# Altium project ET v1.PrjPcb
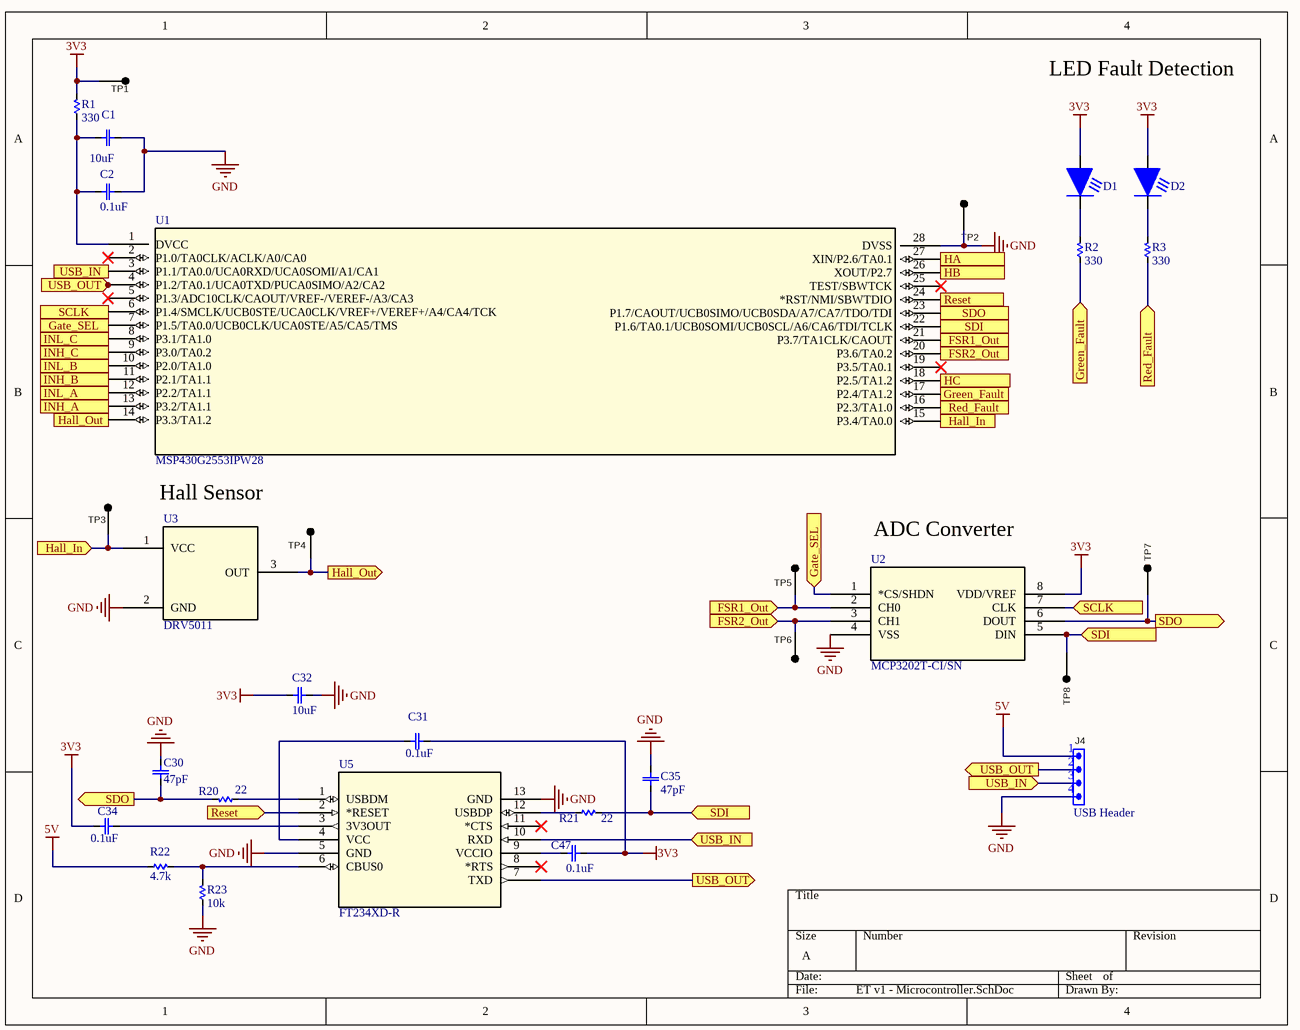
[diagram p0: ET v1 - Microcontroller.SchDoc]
2 sheets, 137 parts. Net scope: flat (ports and power ports of the same name join across sheets).
Board file: ET v1.PcbDoc
Sheets:
  ET v1 - Microcontroller.SchDoc
  ET v1 - GateDriver.SchDoc

## Sheet ET v1 - Microcontroller.SchDoc
size A

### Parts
C1  10uF  [1206]
C2  0.1uF  [1206]
C30  47pF  [0805_HV]
C31  0.1uF  [0805_HV]
C32  10uF  [1206]
C34  0.1uF  [0805_HV]
C35  47pF  [0805_HV]
C47  0.1uF  [0805_HV]
D1  LED  [LED_TH]  (value not drawn)
D2  LED  [LED_TH]  (value not drawn)
J4  USB Header  [USB Header]
R1  330  [0805_HV]
R2  330  [0805_HV]
R3  330  [0805_HV]
R20  22  [0805_HV]
R21  22  [0805_HV]
R22  4.7k  [1206]
R23  10k  [1206]
TP1  Test Point 1  [TP200_SMD]  (value not drawn)  (no BOM)
TP2  Test Point 1  [TP200_SMD]  (value not drawn)  (no BOM)
TP3  Test Point 1  [TP200_SMD]  (value not drawn)  (no BOM)
TP4  Test Point 1  [TP200_SMD]  (value not drawn)  (no BOM)
TP5  Test Point 1  [TP200_SMD]  (value not drawn)  (no BOM)
TP6  Test Point 1  [TP200_SMD]  (value not drawn)  (no BOM)
TP7  Test Point 1  [TP200_SMD]  (value not drawn)  (no BOM)
TP8  Test Point 1  [TP200_SMD]  (value not drawn)  (no BOM)
U1  MSP430G2553IPW28  [MSP430G2353IPW28]
U2  MCP3202T-CI/SN  [MCP3202T-CI/SN]
U3  DRV5011  [Hall_sensor]
U5  FT234XD-R  [FT234XD-R]

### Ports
FSR1_Out (in), FSR1_Out (out), FSR2_Out (in), FSR2_Out (out), Gate_SEL (in), Gate_SEL (out), Green_Fault (in), Green_Fault (out), HA (in), Hall_In (in), Hall_In (out), Hall_Out (in), Hall_Out (out), HB (in), HC (in), INH_A (out), INH_B (out), INH_C (out), INL_A (out), INL_B (out), INL_C (out), Red_Fault (in), Red_Fault (out), Reset (in), Reset (out), SCLK (in), SCLK (out), SDI (in), SDI (out), SDO (in), SDO (out), USB_IN (in), USB_IN (out), USB_OUT (in), USB_OUT (out)

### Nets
3V3: C31.1 C32.2 C34.1 C47.2 D1.1 D2.1 R1.2 TP1.1 U2.8(VDD/VREF)
5V: J4.1 R22.1
GND: C1.2 C2.2 C30.1 C32.1 C35.1 J4.4 R23.1 TP2.1 U1.28(DVSS) U2.4(VSS) U3.2(GND) U5.5(GND) U5.13(GND)
NetC1_1: C1.1 C2.1 R1.1 U1.1(DVCC)
NetC30_2: C30.2 R20.2 TP7.1 U1.23(P1.7/CAOUT/UCB0SIMO/UCB0SDA/A7/CA7/TDO/TDI) U2.6(DOUT) ; port SDO
NetC31_2: C31.2 U5.4(VCC)
NetC33_1: U1.18(P2.5/TA1.2) ; port HC
NetC34_2: C34.2 U5.3(3V3OUT)
NetC35_2: C35.2 R21.2 TP8.1 U1.22(P1.6/TA0.1/UCB0SOMI/UCB0SCL/A6/CA6/TDI/TCLK) U2.5(DIN) ; port SDI
NetC37_1: U1.26(XOUT/P2.7) ; port HB
NetC38_1: U1.27(XIN/P2.6/TA0.1) ; port HA
NetC47_1: C47.1 U5.9(VCCIO)
NetD1_2: D1.2 R2.2
NetD2_2: D2.2 R3.2
NetJ4_2: J4.2 U1.4(P1.2/TA0.1/UCA0TXD/PUCA0SIMO/A2/CA2) U5.7(TXD) ; port USB_OUT
NetJ4_3: J4.3 U1.3(P1.1/TA0.0/UCA0RXD/UCA0SOMI/A1/CA1) U5.10(RXD) ; port USB_IN
NetR2_1: R2.1 U1.17(P2.4/TA1.2) ; port Green_Fault
NetR3_1: R3.1 U1.16(P2.3/TA1.0) ; port Red_Fault
NetR20_1: R20.1 U5.1(USBDM)
NetR21_1: R21.1 U5.12(USBDP)
NetR22_2: R22.2 R23.2 U5.6(CBUS0)
NetTP3_1: TP3.1 U1.15(P3.4/TA0.0) U3.1(VCC) ; port Hall_In
NetTP4_1: TP4.1 U1.14(P3.3/TA1.2) U3.3(OUT) ; port Hall_Out
NetTP5_1: TP5.1 U1.21(P3.7/TA1CLK/CAOUT) U2.2(CH0) ; port FSR1_Out
NetTP6_1: TP6.1 U1.20(P3.6/TA0.2) U2.3(CH1) ; port FSR2_Out
NetTP16_1: U1.7(P1.5/TA0.0/UCB0CLK/UCA0STE/A5/CA5/TMS) U2.1(*CS/SHDN) ; port Gate_SEL
NetTP20_1: U1.13(P3.2/TA1.1) ; port INH_A
NetTP24_1: U1.11(P2.1/TA1.1) ; port INH_B
NetTP25_1: U1.9(P3.0/TA0.2) ; port INH_C
NetU1_6: U1.6(P1.4/SMCLK/UCB0STE/UCA0CLK/VREF+/VEREF+/A4/CA4/TCK) U2.7(CLK) ; port SCLK
NetU1_8: U1.8(P3.1/TA1.0) ; port INL_C
NetU1_10: U1.10(P2.0/TA1.0) ; port INL_B
NetU1_12: U1.12(P2.2/TA1.1) ; port INL_A
NetU1_24: U1.24(*RST/NMI/SBWTDIO) U5.2(*RESET) ; port Reset

Not connected (* = marked no-connect by the designer): U1 2(P1.0/TA0CLK/ACLK/A0/CA0)* 5(P1.3/ADC10CLK/CAOUT/VREF-/VEREF-/A3/CA3)* 19(P3.5/TA0.1)* 25(TEST/SBWTCK)*; U5 8(*RTS)* 11(*CTS)*

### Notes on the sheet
- LED Fault Detection
- Hall Sensor
- (near U2) ADC Converter

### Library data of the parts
C1 = C_10uF_CL31B106KOHVPJE: MLCC10UF16V 10 X7R1206; Manufacturer: TDK; Manufacturer Part Number: C3216X7R1V106M160AC; Voltage Rating: 35V; Tolerance: 20%; Dielectric: X7R; Dielectric Material: Ceramic
C2 = C_0.1uF 885012206020 CAP CER 0.1UF 10V X7R 0603: CAP CER 0.1UF 10V X7R 0603; Manufacturer: TDK; Manufacturer Part Number: C3216X7R2A104K160AA; Capacitance: 100nF; Tolerance: 10%; Voltage Rating: 100V
C30 C35 = C_47pF_C0805C470K5RAC7800: CAP CER 47PF 50V X7R 0805; Manufacturer: Samsung; Manufacturer Part Number: CL05A105MO5NNNC; Capacitance: 1uF; Tolerance: 20%; Voltage Rating: 16V
C31 C34 = C_0.1uF_C0805C104K6RAC7800: CAP CER SMD 0805 .1UF 35V 10% X7; Manufacturer: Wurth Electronics; Manufacturer Part Number: 885012105013; Capacitance: 2.2uF; Voltage Rating: 10V; Tolerance: 20%
C32 = C_10uF_CL31B106KOHVPJE: MLCC10UF16V 10 X7R1206; Manufacturer: TDK; Manufacturer Part Number: C3216X7R1V106M160AC; Dielectric Material: Ceramic; Voltage Rating: 35V; Tolerance: 20%; Dielectric: X7R
C47 = C_0.1uF_C0805C104K6RAC7800: CAP CER SMD 0805 .1UF 35V 10% X7
J4 = USB Header: 2.54mm pitch, 1mm hole; Manufacturer: Phoenix Contact; Manufacturer Part Number: 1904150; Number of Positions: 3; Gender: Male; Max Current Rating: 32A; Voltage Rating: 1kV; Number of Levels: 1; Current: 30A; Voltage: 600V; Max Supply Voltage: 800V; Pitch: 9.52mm; Wire Gauge (Max): 30AWG; Wire Gauge (Min): 10AWG; Wire/Cable Gauge: 24AWG; Approvals: CB
R1-R3 = R_ 330_ERJ-P6WJ331V: 330 Ohms ±1% 0.5W, 1/2W Chip Resistor 0805 (2012 Metric) Automotive AEC-Q200, Pulse Withstanding Thick Film
R20 R21 = R_22_ERJ-P06F22R0V: RES SMD 22 OHM 1% 1/2W 0805; Manufacturer: Vishay; Manufacturer Part Number: CRCW060347K0JNEA; Resistance: 47kR; Tolerance: 5%; Temperature Coefficient: 200ppm/°C; Max Power Dissipation: 100mW; Voltage Rating: 75V
R22 = R_4.7k CRGP1206F4K7: RES 4.7K OHM 1% 1/2W 1206; Manufacturer: Panasonic; Manufacturer Part Number: ERJ-2RKF1002X; Resistance: 10kR; Temperature Coefficient: 100ppm/°C; Power Rating: 100mW; Voltage Rating: 50V
R23 = R_10k_RE1206FRE0710KL: RES SMD 10K OHM 1% 1/4W 1206; Manufacturer: Vishay; Manufacturer Part Number: CRCW060347K0JNEA; Resistance: 47kR; Tolerance: 5%; Temperature Coefficient: 200ppm/°C; Max Power Dissipation: 100mW; Voltage Rating: 75V
TP1-TP8 = Test Point 1: Test Point, Round, Surface Pad
U1 = MSP430G2553IPW28: No Description Available; Mfr_Name: Texas Instruments
U2 = MCP3202T-CI/SN: IC ADC 12BIT SAR 8SOIC; Mfr_Name: Microchip
U3 = Hall_Sensor_DRV5011: MAGNETIC SWITCH LATCH TO92-3
U5 = FT234XD-R: IC USB SERIAL BASIC UART 12DFN; Mfr_Name: FTDI, Future Technology Devices International Ltd

## Sheet ET v1 - GateDriver.SchDoc
size B
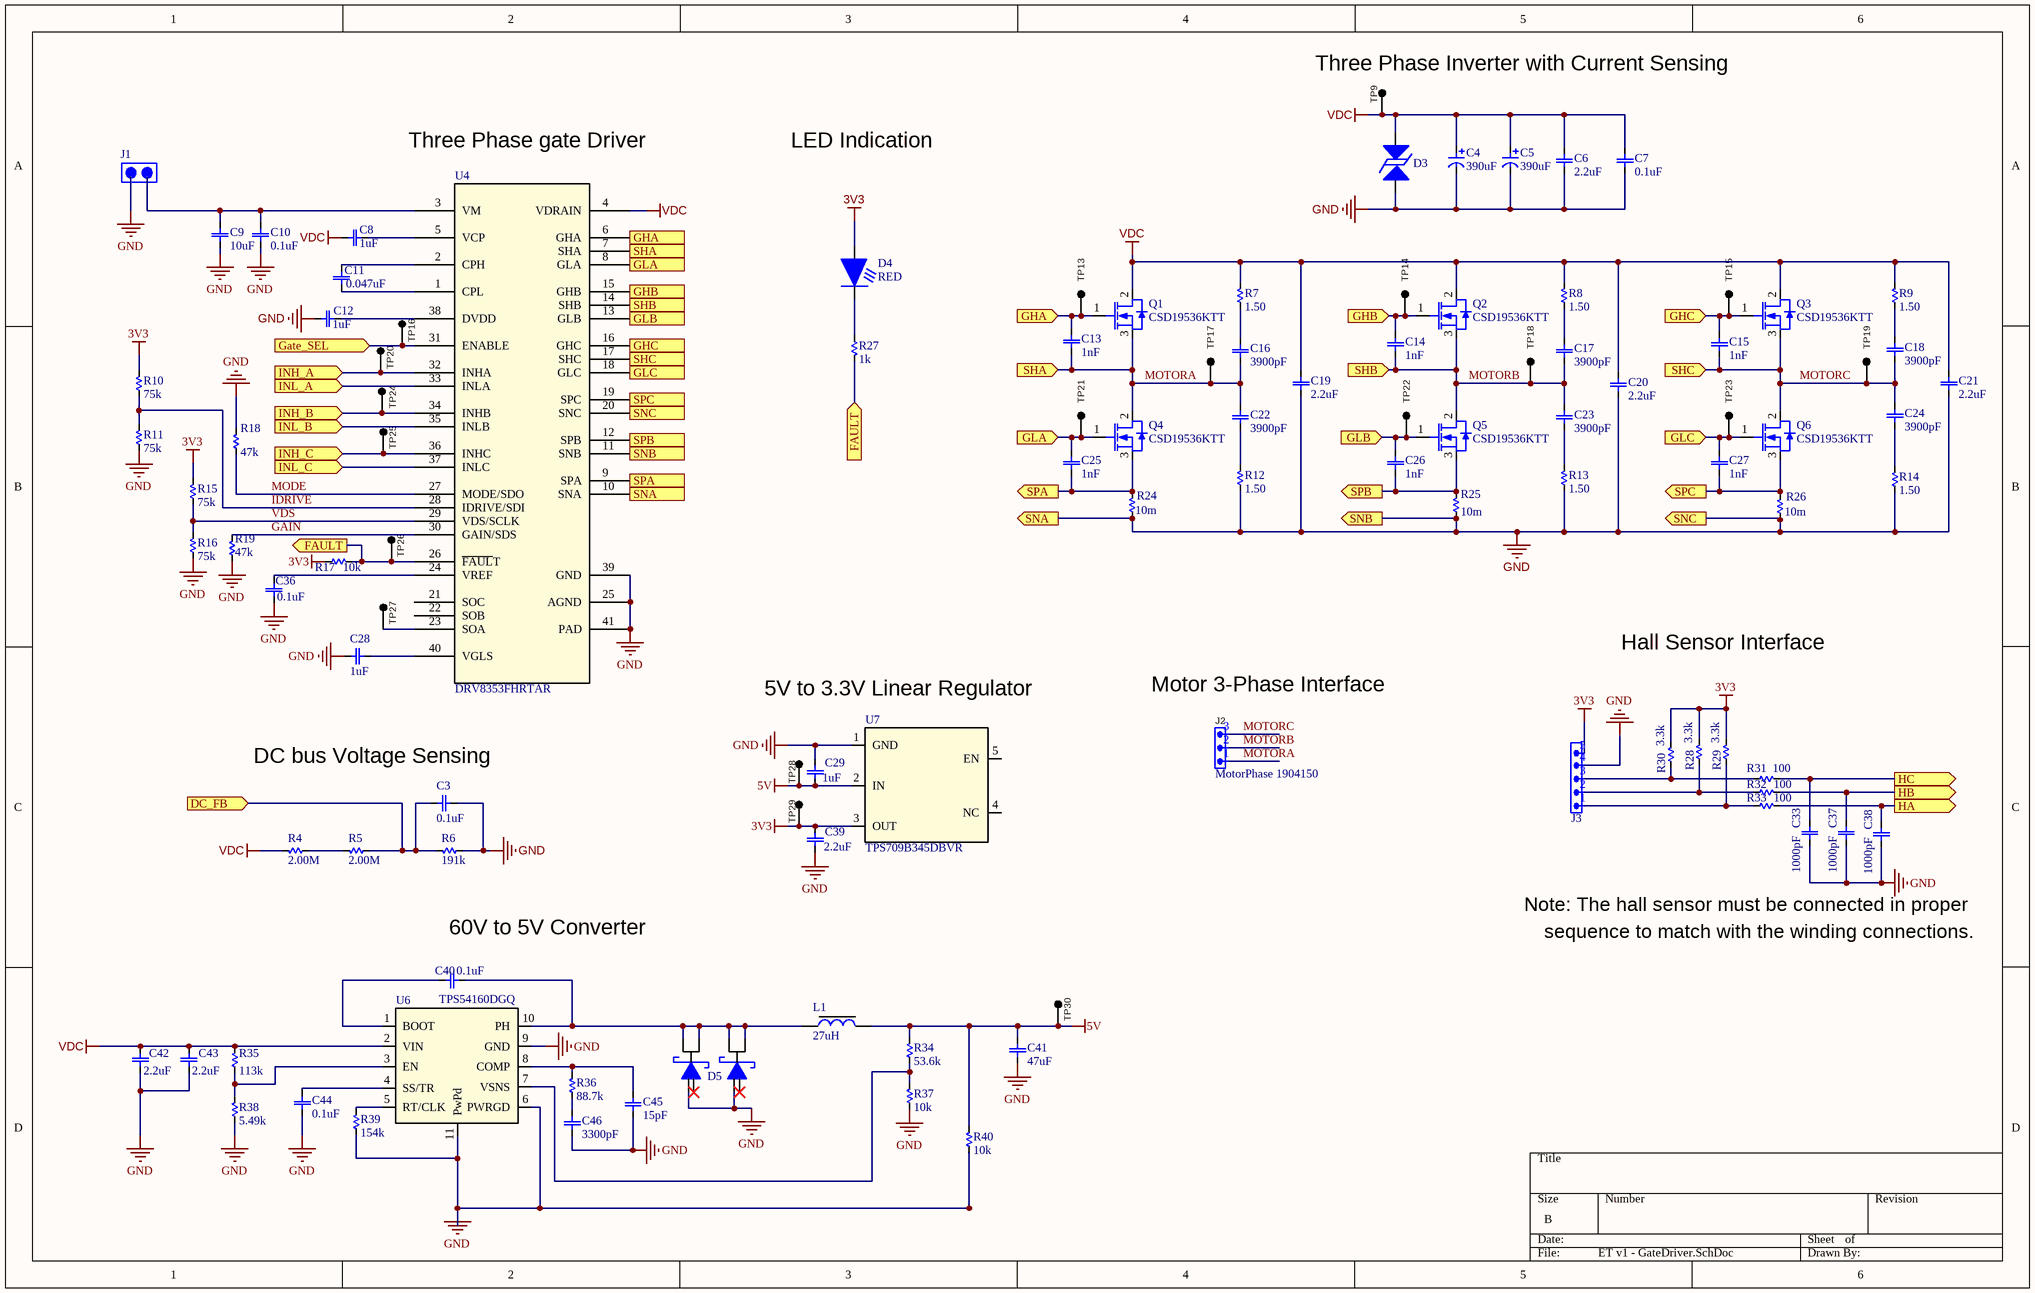
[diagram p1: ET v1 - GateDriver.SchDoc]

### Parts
C3  0.1uF  [1206]
C4  390uF  [YXJ_1600x2500]
C5  390uF  [YXJ_1600x2500]
C6  2.2uF  [1206]
C7  0.1uF  [1206]
C8  1uF  [0805_HV]
C9  10uF  [2220_280]
C10  0.1uF  [0603]
C11  0.047uF  [0805_HV]
C12  1uF  [0805_HV]
C13  1nF  [0603]
C14  1nF  [0603]
C15  1nF  [0603]
C16  3900pF  [1206]
C17  3900pF  [1206]
C18  3900pF  [1206]
C19  2.2uF  [1206]
C20  2.2uF  [1206]
C21  2.2uF  [1206]
C22  3900pF  [1206]
C23  3900pF  [1206]
C24  3900pF  [1206]
C25  1nF  [0603]
C26  1nF  [0603]
C27  1nF  [0603]
C28  1uF  [0805_HV]
C29  1uF  [0805_HV]
C33  1000pF  [0805_HV]
C36  0.1uF  [1206]
C37  1000pF  [0805_HV]
C38  1000pF  [0805_HV]
C39  2.2uF  [1206]
C40  0.1uF  [1206]
C41  47uF  [0805_HV]
C42  2.2uF  [0402]
C43  2.2uF  [0402]
C44  0.1uF  [1206]
C45  15pF  [0805_HV]
C46  3300pF  [0805_HV]
D3  SMBJ70CA-13-F  [SMB-Bi]  (value not drawn)
D4  RED  [WL-SMCW_GREEN]
D5  V8KM60DUHM3/H  [V8KM60DUHM3/H]  (value not drawn)
J1  XT60 PRT-10474  [XT60 PRT-10474]  (value not drawn)
J2  MotorPhase 1904150  [MotorPhase 1904150]
J3  MotorHall_1792892  [MotorHall_1792892]  (value not drawn)
L1  27uH  [MSS1038T-273MLC]
Q1  CSD19536KTT  [KTT0002A]
Q2  CSD19536KTT  [KTT0002A]
Q3  CSD19536KTT  [KTT0002A]
Q4  CSD19536KTT  [KTT0002A]
Q5  CSD19536KTT  [KTT0002A]
Q6  CSD19536KTT  [KTT0002A]
R4  2.00M  [0402]
R5  2.00M  [0402]
R6  191k  [0603]
R7  1.50  [1206]
R8  1.50  [1206]
R9  1.50  [1206]
R10  75k  [0603]
R11  75k  [0603]
R12  1.50  [1206]
R13  1.50  [1206]
R14  1.50  [1206]
R15  75k  [0603]
R16  75k  [0603]
R17  10k  [0603]
R18  47k  [0603]
R19  47k  [0603]
R24  10m  [2512]
R25  10m  [2512]
R26  10m  [2512]
R27  1k  [0805_HV]
R28  3.3k  [0805_HV]
R29  3.3k  [0805_HV]
R30  3.3k  [0805_HV]
R31  100  [0805_HV]
R32  100  [0805_HV]
R33  100  [0805_HV]
R34  53.6k  [0805_HV]
R35  113k  [0805_HV]
R36  88.7k  [0805_HV]
R37  10k  [1206]
R38  5.49k  [0805_HV]
R39  154k  [0805_HV]
R40  10k  [1206]
TP9  Test Point 1  [TP200_SMD]  (value not drawn)  (no BOM)
TP13  Test Point 1  [TP200_SMD]  (value not drawn)  (no BOM)
TP14  Test Point 1  [TP200_SMD]  (value not drawn)  (no BOM)
TP15  Test Point 1  [TP200_SMD]  (value not drawn)  (no BOM)
TP16  Test Point 1  [TP200_SMD]  (value not drawn)  (no BOM)
TP17  Test Point 1  [TP200_SMD]  (value not drawn)  (no BOM)
TP18  Test Point 1  [TP200_SMD]  (value not drawn)  (no BOM)
TP19  Test Point 1  [TP200_SMD]  (value not drawn)  (no BOM)
TP20  Test Point 1  [TP200_SMD]  (value not drawn)  (no BOM)
TP21  Test Point 1  [TP200_SMD]  (value not drawn)  (no BOM)
TP22  Test Point 1  [TP200_SMD]  (value not drawn)  (no BOM)
TP23  Test Point 1  [TP200_SMD]  (value not drawn)  (no BOM)
TP24  Test Point 1  [TP200_SMD]  (value not drawn)  (no BOM)
TP25  Test Point 1  [TP200_SMD]  (value not drawn)  (no BOM)
TP26  Test Point 1  [TP200_SMD]  (value not drawn)  (no BOM)
TP27  Test Point 1  [TP200_SMD]  (value not drawn)  (no BOM)
TP28  Test Point 1  [TP200_SMD]  (value not drawn)  (no BOM)
TP29  Test Point 1  [TP200_SMD]  (value not drawn)  (no BOM)
TP30  Test Point 1  [TP200_SMD]  (value not drawn)  (no BOM)
U4  DRV8353FHRTAR  [DRV8353FHRTAR]
U6  TPS54160DGQ  [TPS54160DGQ]
U7  TPS709B345DBVR  [TPS709B345DBVR]

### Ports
DC_FB (in), FAULT (in), FAULT (out), Gate_SEL (in), GHA (in), GHA (out), GHB (in), GHB (out), GHC (in), GHC (out), GLA (in), GLA (out), GLB (in), GLB (out), GLC (in), GLC (out), HA (out), HB (out), HC (out), INH_A (in), INH_B (in), INH_C (in), INL_A (in), INL_B (in), INL_C (in), SHA (in), SHB (in), SHC (in), SNA (in), SNA (out), SNB (in), SNB (out), SNC (in), SNC (out), SPA (in), SPA (out), SPB (in), SPB (out), SPC (in), SPC (out)

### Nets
3V3: C39.2 D4.1 J3.5 R10.2 R15.2 R17.1 R28.2 R29.2 R30.2 TP29.1 U7.3(OUT)
5V: C29.1 C41.2 L1.2 R34.2 R40.2 TP28.1 TP30.1 U7.2(IN)
GND: C3.1 C4.2 C5.2 C6.1 C7.1 C9.1 C10.1 C12.1 C19.1 C20.1 C21.1 C28.1 C29.2 C33.2 C36.1 C37.2 C38.2 C39.1 C41.1 C42.1 C43.1 C44.1 C45.1 C46.1 D3.1 D5.1 D5.3 J1.1 J3.4 R6.1 R11.1 R12.1 R13.1 R14.1 R16.1 R18.2 R19.1 R24.1 R25.1 R26.1 R37.1 R38.1 R39.1 R40.1 U4.10(SNA) U4.11(SNB) U4.20(SNC) U4.25(AGND) U4.39(GND) U4.41(PAD) U6.6(PWRGD) U6.9(GND) U6.11(PwPd) U7.1(GND) ; port SNC, port SNB, port SNA
VDC: C4.1 C5.1 C6.2 C7.2 C8.1 C19.2 C20.2 C21.2 C42.2 C43.2 D3.2 Q1.2 Q2.2 Q3.2 R4.2 R7.2 R8.2 R9.2 R35.2 TP9.1 U4.4(VDRAIN) U6.2(VIN)
GAIN: R19.2 U4.30(GAIN/SDS)
IDRIVE: R10.1 R11.2 U4.28(IDRIVE/SDI)
MODE: R18.1 U4.27(MODE/SDO)
MOTORA: C13.1 C16.1 C22.2 J2.1 Q1.3 Q4.2 TP17.1 U4.7(SHA) ; port SHA
MOTORB: C14.1 C17.1 C23.2 J2.2 Q2.3 Q5.2 TP18.1 U4.14(SHB) ; port SHB
MOTORC: C15.1 C18.1 C24.2 J2.3 Q3.3 Q6.2 TP19.1 U4.17(SHC) ; port SHC
VDS: R15.1 R16.2 U4.29(VDS/SCLK)
NetC3_2: C3.2 R5.1 R6.2 ; port DC_FB
NetC8_2: C8.2 U4.5(VCP)
NetC9_2: C9.2 C10.2 J1.2 U4.3(VM)
NetC11_1: C11.1 U4.1(CPL)
NetC11_2: C11.2 U4.2(CPH)
NetC12_2: C12.2 U4.38(DVDD)
NetC13_2: C13.2 Q1.1 TP13.1 U4.6(GHA) ; port GHA
NetC14_2: C14.2 Q2.1 TP14.1 U4.15(GHB) ; port GHB
NetC15_2: C15.2 Q3.1 TP15.1 U4.16(GHC) ; port GHC
NetC16_2: C16.2 R7.1
NetC17_2: C17.2 R8.1
NetC18_2: C18.2 R9.1
NetC22_1: C22.1 R12.2
NetC23_1: C23.1 R13.2
NetC24_1: C24.1 R14.2
NetC25_1: C25.1 Q4.3 R24.2 U4.9(SPA) ; port SPA
NetC25_2: C25.2 Q4.1 TP21.1 U4.8(GLA) ; port GLA
NetC26_1: C26.1 Q5.1 TP22.1 U4.13(GLB) ; port GLB
NetC26_2: C26.2 Q5.3 R25.2 U4.12(SPB) ; port SPB
NetC27_1: C27.1 Q6.3 R26.2 U4.19(SPC) ; port SPC
NetC27_2: C27.2 Q6.1 TP23.1 U4.18(GLC) ; port GLC
NetC28_2: C28.2 U4.40(VGLS)
NetC33_1: C33.1 R31.2 ; port HC
NetC36_2: C36.2 U4.24(VREF)
NetC37_1: C37.1 R32.2 ; port HB
NetC38_1: C38.1 R33.2 ; port HA
NetC40_1: C40.1 U6.1(BOOT)
NetC40_2: C40.2 D5.5 D5.6 D5.7 D5.8 L1.1 U6.10(PH)
NetC44_2: C44.2 U6.4(SS/TR)
NetC45_2: C45.2 R36.2 U6.8(COMP)
NetC46_2: C46.2 R36.1
NetD4_2: D4.2 R27.1
NetJ3_1: J3.1 R29.1 R33.1
NetJ3_2: J3.2 R28.1 R32.1
NetJ3_3: J3.3 R30.1 R31.1
NetR4_1: R4.1 R5.2
NetR17_2: R17.2 R27.2 TP26.1 U4.26(~{FAUL}T) ; port FAULT
NetR34_1: R34.1 R37.2 U6.7(VSNS)
NetR35_1: R35.1 R38.2 U6.3(EN)
NetR39_2: R39.2 U6.5(RT/CLK)
NetTP16_1: TP16.1 U4.31(ENABLE) ; port Gate_SEL
NetTP20_1: TP20.1 U4.32(INHA) ; port INH_A
NetTP24_1: TP24.1 U4.34(INHB) ; port INH_B
NetTP25_1: TP25.1 U4.36(INHC) ; port INH_C
NetTP27_1: TP27.1 U4.23(SOA)
NetU1_8: U4.37(INLC) ; port INL_C
NetU1_10: U4.35(INLB) ; port INL_B
NetU1_12: U4.33(INLA) ; port INL_A

Not connected (* = marked no-connect by the designer): D5 2* 4*; U4 21(SOC) 22(SOB); U7 4(NC) 5(EN)

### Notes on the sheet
- (near TP9) Three Phase Inverter with Current Sensing
- Three Phase gate Driver
- LED Indication
- Hall Sensor Interface
- 5V to 3.3V Linear Regulator
- (near J2) Motor 3-Phase Interface
- (near C3) DC bus Voltage Sensing
- Note: The hall sensor must be connected in proper
- 60V to 5V Converter
- sequence to match with the winding connections.

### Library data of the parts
C3 = C_0.1uF 885012208009: CAP CER 0.1UF 10V X7R 1206
C4 C5 = C_390uF EEU-FS2A391: CAP ALUM 390UF 20% 100V THRUHOLE; Manufacturer: Panasonic
C6 C19-C21 C39 = C_2.2uF CL31B225KCHSNNE: Cap Ceramic 2.2uF 100V X7R 10% Pad SMD 1206 Soft Termination 125C T/R; Manufacturer: Samsung
C7 = C_0.1uF C3216X7R2A104K160AA: CAP CER 0.1UF 100V X7R 1206; Manufacturer: TDK; Capacitance: 100nF; Tolerance: 10%
C8 C28 C29 = C_1uF CGA4J2X5R1C105M125AA: 1 µF ±20% 16V Ceramic Capacitor X5R 0805 (2012 Metric)
C9 = C_10uF 22201C106MAT2A: Cap Ceramic 10uF 100V X7R 20% SMD 2220 125°C Embossed T/R; Manufacturer: Kyocera AVX; Number of Outputs: 1; Output Voltage: 58V; Output Current: 1.5A; Switching Frequency: 581kHz; Max Input Voltage: 60V; Min Input Voltage: 3.5V; Synchronous Rectifier: No; Min Output Voltage: 800mV; Quiescent Current: 116uA; Output Type: Adjustable; Topology: Buck-Boost
C10 = C_0.1uF GRM188R72A104KA35D: 0603 0.1 uF 100 V ±10 % Tolerance X7R SMT Multilayer Ceramic Capacitor; Manufacturer: Murata; Capacitance: 100nF; Tolerance: 10%; Voltage Rating: 100V
C11 = C_0.047uF GRM21BR72A473KA01L: Cap Ceramic 0.047uF 100V X7R 10% SMD 0805 125C Embossed T/R; Manufacturer: Murata; Capacitance: 47nF
C12 = C_1uF LGC26D105MAT2S1: CAP CER 1UF 6.3V X5R 0805
C13-C15 C25-C27 = C_1nF 885012206083: CAP, CERM, 1000 pF, 50 V,+/- 10%, X7R, 0603
C16-C18 C22-C24 = C_3900pF 12061C392KAZ2A: CAP CER 3900PF 100V X7R 1206
C33 C37 C38 = C_1000pF CC0805JRNPO9BN102: Capacitor 1NF 50V 0805 SMD Npo (reel); Manufacturer: Yageo; Dielectric Material: Ceramic; Tolerance: 5%; Dielectric: C0G; Insulation Resistance: 10GR; Temperature Coefficient: 30ppm/°C; Dissipation Factor: 0.1%
C36 C40 C44 = C_0.1uF 885012206020 CAP CER 0.1UF 10V X7R 0603: as C2 on sheet ET v1 - Microcontroller
C41 = C_47uF C0805C476M9PACTU: Cap Ceramic 47uF 6.3V X5R 20% SMD 0805 Plastic T/R; Manufacturer: KEMET; Dissipation Factor: 5%
C42 C43 = C_2.2uF 885012105013: Cap, 2.2UF, 10V, 20%, X5R, 0402; Manufacturer: Wurth Electronics
C45 = C_15pF 08055A150GAT2A: Capacitor, ceramic, 15Pf, 50Vdc, 2-% Tol, 2+% Tol, c0G-Tc Code, -30, 30Ppm-Tc Rohs Compliant: Yes; Manufacturer: Kyocera AVX; Tolerance: 2%; Dielectric: C0G; Voltage Rating: 50V
C46 = C_3300pF 885012207119: Cap, 3300PF, 100V, 10%, X7R, 0805; Manufacturer: Wurth Electronics; Capacitance: 3.3nF
D3 = Diode SMBJ70CA-13-F: Diode TVS Single Bi-Dir 70V 600W 2-Pin SMB T/R; Manufacturer: Diodes; Manufacturer Part Number: SMBJ7.0CA-13-F; Number of Terminals/Pins: 2; Package Body Material: Plastic; Diode Element Material: SILICON; Min Breakdown Voltage: 77.8V; Clamping Voltage: 113V; Peak Pulse Current: 5.3A; Direction: Bidirectional; Max Reverse Leakage Current: 5uA; Test Current: 1mA; Max Breakdown Voltage: 89.5V; Reverse Breakdown Voltage: 7.78V; Number of Elements: 1; Power Line Protection: No; Leakage Current: 400uA; Voltage Rating (DC): 7V; Diode Type: ZENER; Time @ Peak Reflow Temperature-Max (s): 5s
D4 = LED_Red 150060RS75000: LED Low-Power Uni-Color Red 630nm 2V 2-Pin Chip 0603(1608Metric) T/R; Manufacturer: Wurth Electronics; Viewing Angle: 140°; Lens Style: Clear,Rectangular; Luminous Intensity: 250mcd; Forward Current: 30mA; Wavelength: 625nm; Test Current: 20mA
D5 = Diode V8KM60DUHM3/H: Diode Array 2 Independent Schottky 60 V 8A Surface Mount 8-PowerTDFN
J1 = XT60 PRT-10474: XT60 Connectors Male/female Pair; Manufacturer: SparkFun
J2 = MotorPhase 1904150: Conn PC Terminal Block 3 POS 9.52mm Solder ST Thru-Hole 32A; Manufacturer: Phoenix Contact; Number of Positions: 3; Gender: Male; Voltage Rating: 1kV; Number of Levels: 1; Current: 30A; Voltage: 600V; Max Supply Voltage: 800V; Wire Gauge (Max): 30AWG; Wire Gauge (Min): 10AWG; Wire/Cable Gauge: 24AWG; Approvals: CB
J3 = MotorHall_1792892: Wire-To-Board Terminal Block, 5, 400 V, 12 A, 26 Awg, 14 Awg, 2.5 Mm Rohs Compliant: Yes; Manufacturer: Phoenix Contact; Current Rating: 10A; Voltage Rating: 300V; Number of Contacts: 5; Number of Levels: 1; Wire Gauge (Max): 26AWG; Wire Gauge (Min): 14AWG; Pitch: 5mm; Stripping Length: 8mm; Approvals: VDE,cULus,CB,EAC
L1 = L_27uH MSS1038T-273MLC: Power inductor, shielded, 10/20/30% tol, SMT, RoHS; Manufacturer: Coilcraft; Core Material: Ferrite; Inductance Tolerance: 20%; Self Resonant Frequency: 15MHz; Max DC Current: 2.35A; DC Resistance (DCR): 89mR; Test Frequency: 100kHz; Saturation Current: 1.98A
Q1-Q6 = MOSFET CSD19536KTT: This 100 V, 2.0 m D2PAK (TO-263) NexFET power MOSFET is designed to minimize losses in power conversion applications.; Manufacturer: Texas Instruments; Drain to Source Voltage (Vdss): 100V; Continuous Drain Current (ID): 200A; Rds On Max: 2.4mR; Input Capacitance: 12nF; Max Power Dissipation: 375W; Fall Time: 6ns; Gate to Source Voltage (Vgs): 20V; Rise Time: 8ns; Turn-On Delay Time: 13ns; Turn-Off Delay Time: 32ns; Element Configuration: Single
R4 R5 = R_2M CRCW04022M00FKED: Res Thick Film 0402 2M Ohm 1% 1/16W ±100ppm/°C Molded SMD SMD Paper T/R; Manufacturer: Vishay; Resistance: 2MR; Power Rating: 63mW; Voltage Rating: 50V
R6 = R_191k RC0603FR-07191KL: RES 191K OHM 1% 1/10W 0603
R7-R9 R12-R14 = R_1.50 CRCW12061R50FKEA: Thick Film Resistors - SMD 1/4watt 1.5ohms 1%; Manufacturer: Vishay Dale; Resistance: 1.5R; Temperature Coefficient: 100ppm/°C; Power Rating: 250mW; Voltage Rating: 200V
R10 R11 R15 R16 = R_75k CRCW060375K0JNEA: Res Thick Film 0603 75K Ohm 5% 1/10W ±200ppm/°C Molded SMD SMD Paper T/R; Manufacturer: Vishay Dale; Resistance: 75kR; Max Power Dissipation: 100mW; Voltage Rating: 75V
R17 = R_10k RC0603FR-0710KL: RES 10K OHM 1% 1/10W 0603
R18 R19 = R_47k CRCW060347K0JNEA: Res Thick Film 0603 47K Ohm 5% 1/10W ±200ppm/°C Molded SMD SMD Paper T/R; Manufacturer: Vishay; Resistance: 47kR; Max Power Dissipation: 100mW; Voltage Rating: 75V
R24-R26 = R_10m CSR2512A0R01F: Res 2512 0.01 Ohm 1% 2W ±50/±75ppm/C Pad SMD T/R; Manufacturer: Riedon; Resistance: 10mR; Temperature Coefficient: 50ppm/°C
R27 = R_1k CR0805-FX-1001ELF: Res Thick Film 0805 1K Ohm 1% 1/8W ±100ppm/°C Molded SMD SMD Paper Tape on Plastic Reel; Manufacturer: Bourns; Resistance: 1kR; Power Rating: 125mW; Voltage Rating: 150V
R28-R30 = R_3.3k SR0805FR-473K3L: Res Thick Film 0805 3.3K Ohm 1% 0.5W(1/2W) ±100ppm/°C Pad SMD Automotive T/R; Manufacturer: Yageo
R31-R33 = R_100 SR0805JR-47100RL: Res Thick Film 0805 100 Ohm 5% 0.5W(1/2W) ±100ppm/C Pad SMD Automotive T/R; Manufacturer: Yageo
R34 = R_53.6k RT0805FRE0753K6L: High Precision-High Stability Chip Resistor Thin Film 0805 53.6kOhm 1% Paper T/R; Manufacturer: Yageo; Resistance: 53.6kR; Power Rating: 125mW; Voltage Rating: 150V; Temperature Coefficient: 50ppm/°C
R35 = R_113k CRCW0805113KFKEA: Res Thick Film 0805 113K Ohm 1% 1/8W ±100ppm/°C Molded SMD SMD Paper T/R; Manufacturer: Vishay; Resistance: 113kR; Max Power Dissipation: 125mW; Voltage Rating: 150V
R36 = R_88.7k RC0805FR-0788K7L: Res Thick Film 0805 88.7K Ohm 1% 0.125W(1/8W) ±100ppm/C Pad SMD T/R; Manufacturer: Yageo; Resistance: 88.7kR; Power Rating: 125mW; Voltage Rating: 150V; Temperature Coefficient: 100ppm/°C
R37 R40 = R_10k_RE1206FRE0710KL: as R23 on sheet ET v1 - Microcontroller
R38 = R_5.49k RC0805FR-075K49L: Res Thick Film 2.0 x 1.2 mm 5.49K Ohm 1% 0.125W(1/8W) 100ppm/ C Molded SMD Paper T/R; Manufacturer: Yageo; Power Rating: 125mW; Resistance: 5.49kR; Voltage Rating: 150V; Temperature Coefficient: 100ppm/°C
R39 = R_154k RC0805FR-07154KL: Res Thick Film 2.0 x 1.2 mm 154K Ohm 1% 0.125W(1/8W) 100ppm/ C Molded SMD Paper T/R; Manufacturer: Yageo; Resistance: 154kR; Temperature Coefficient: 100ppm/°C; Power Rating: 125mW; Voltage Rating: 150V
TP9 TP13-TP30 = Test Point 1: Test Point, Round, Surface Pad
U6 = TPS54160DGQ: 3.5V to 60V Input, 1.5A Step-Down Converter with Eco-Mode 10-HVSSOP -40 to 150; Manufacturer: Texas Instruments; Number of Outputs: 1; Output Voltage: 58V; Switching Frequency: 581kHz; Synchronous Rectifier: No; Min Output Voltage: 800mV; Quiescent Current: 116uA; Output Type: Adjustable; Topology: Buck-Boost
U7 = TPS709B345DBVR: Voltage Regulator with Enable 3.45V 150mA 1uA IQ 5-Pin SOT-23 T/R; Manufacturer: Texas Instruments

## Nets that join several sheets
3V3: ET v1 - Microcontroller (9 pins), ET v1 - GateDriver (11 pins)
5V: ET v1 - Microcontroller (J4.1 R22.1), ET v1 - GateDriver (8 pins)
GND: ET v1 - Microcontroller (13 pins), ET v1 - GateDriver (54 pins)
NetC33_1: ET v1 - Microcontroller (U1.18), ET v1 - GateDriver (C33.1 R31.2)
NetC37_1: ET v1 - Microcontroller (U1.26), ET v1 - GateDriver (C37.1 R32.2)
NetC38_1: ET v1 - Microcontroller (U1.27), ET v1 - GateDriver (C38.1 R33.2)
NetTP16_1: ET v1 - Microcontroller (U1.7 U2.1), ET v1 - GateDriver (TP16.1 U4.31)
NetTP20_1: ET v1 - Microcontroller (U1.13), ET v1 - GateDriver (TP20.1 U4.32)
NetTP24_1: ET v1 - Microcontroller (U1.11), ET v1 - GateDriver (TP24.1 U4.34)
NetTP25_1: ET v1 - Microcontroller (U1.9), ET v1 - GateDriver (TP25.1 U4.36)
NetU1_8: ET v1 - Microcontroller (U1.8), ET v1 - GateDriver (U4.37)
NetU1_10: ET v1 - Microcontroller (U1.10), ET v1 - GateDriver (U4.35)
NetU1_12: ET v1 - Microcontroller (U1.12), ET v1 - GateDriver (U4.33)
